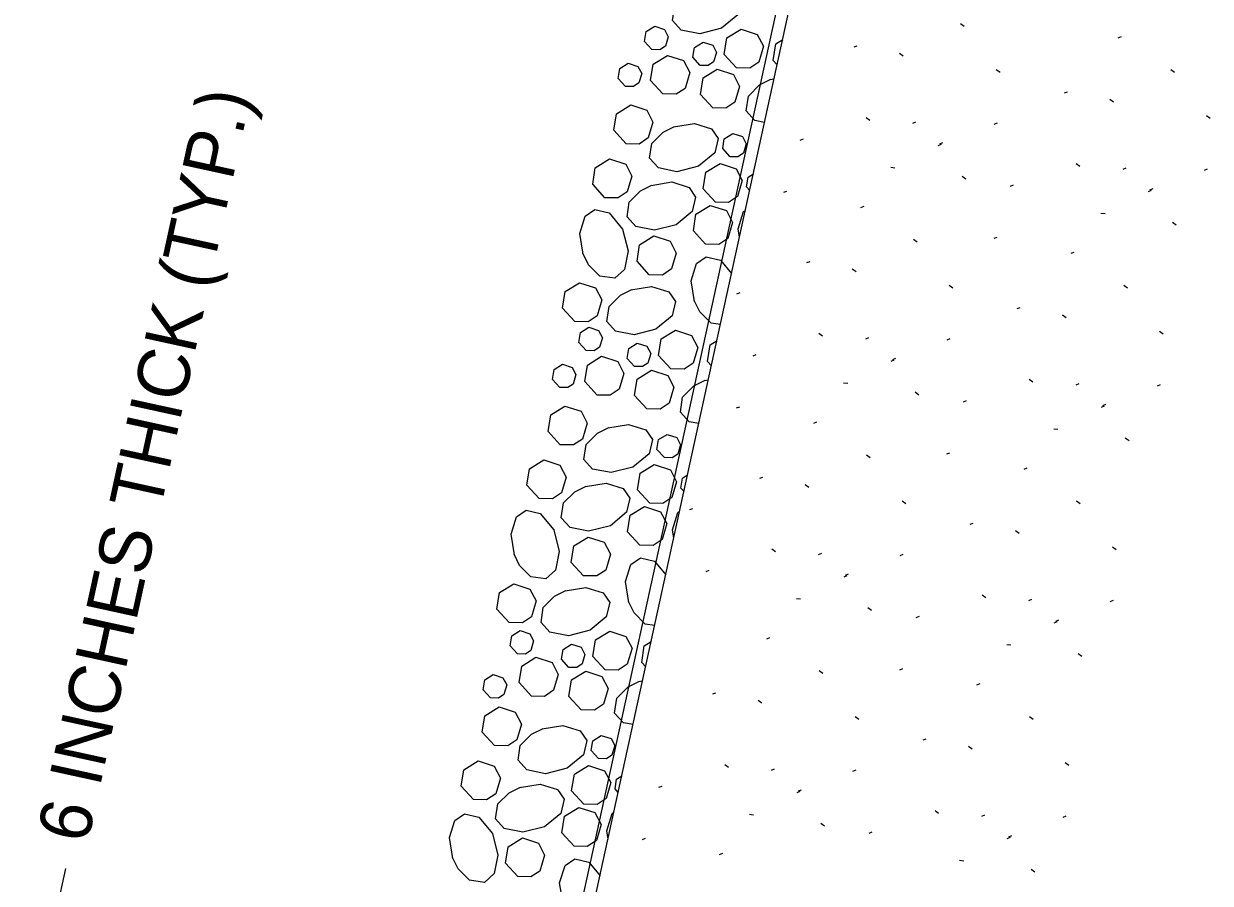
# Model space of a CAD drawing. Extents: x 2126110 to 2128246, y 1804858 to 1811658.
# Drawn here: x 2126769.3 to 2126883.6, y 1806418.7 to 1806501.5 of the extents above; entities that cross this region are included whole.
import ezdxf

# ---------------------------------------------------------------- set-up
doc = ezdxf.new("R2010")
doc.units = 0
doc.layers.add('1', color=7, linetype='Continuous')

msp = doc.modelspace()

# ---------------------------------------------------------------- linework, layer by layer
at = {"layer": '1'}
for p, q in [((2126821.03, 1806407.52), (2126844.25, 1806513.73)), ((2126822.04, 1806406.65), (2126845.41, 1806513.57)), ((2126859.94, 1806501.26), (2126859.59, 1806501.52)), ((2126874.78, 1806500.18), (2126875.08, 1806500.3)), ((2126849.32, 1806499.29), (2126849.62, 1806499.41)), ((2126854.05, 1806498.41), (2126853.69, 1806498.67)), ((2126863.39, 1806496.82), (2126863.03, 1806497.08)), ((2126880.2, 1806496.83), (2126879.85, 1806497.09)), ((2126841.22, 1806496.15), (2126841.62, 1806496.22)), ((2126869.59, 1806494.86), (2126869.89, 1806494.98)), ((2126874.31, 1806493.98), (2126873.96, 1806494.24)), ((2126850.83, 1806492.2), (2126850.48, 1806492.46)), ((2126854.98, 1806491.96), (2126855.28, 1806492.07)), ((2126862.83, 1806491.86), (2126863.13, 1806491.97)), ((2126883.65, 1806492.4), (2126883.3, 1806492.65)), ((2126844.13, 1806490.31), (2126844.43, 1806490.43)), ((2126857.44, 1806489.81), (2126857.74, 1806489.92)), ((2126857.58, 1806489.96), (2126857.87, 1806490.07)), ((2126852.85, 1806487.71), (2126853.25, 1806487.66)), ((2126871.09, 1806487.78), (2126870.74, 1806488.04)), ((2126875.25, 1806487.53), (2126875.55, 1806487.65)), ((2126883.1, 1806487.43), (2126883.39, 1806487.55)), ((2126860.1, 1806486.54), (2126859.74, 1806486.8)), ((2126842.54, 1806485.29), (2126842.84, 1806485.4)), ((2126864.4, 1806485.88), (2126864.69, 1806486)), ((2126877.7, 1806485.38), (2126878, 1806485.49)), ((2126877.84, 1806485.53), (2126878.14, 1806485.65)), ((2126849.98, 1806483.83), (2126850.28, 1806483.95)), ((2126873.11, 1806483.28), (2126873.51, 1806483.24)), ((2126880.36, 1806482.12), (2126880.01, 1806482.37)), ((2126855.4, 1806480.48), (2126855.05, 1806480.74)), ((2126862.81, 1806480.86), (2126863.11, 1806480.98)), ((2126870.24, 1806479.41), (2126870.54, 1806479.52)), ((2126844.78, 1806478.51), (2126845.08, 1806478.63)), ((2126849.51, 1806477.63), (2126849.15, 1806477.89)), ((2126858.85, 1806476.04), (2126858.49, 1806476.3)), ((2126875.66, 1806476.05), (2126875.31, 1806476.31)), ((2126838.03, 1806475.51), (2126838.33, 1806475.62)), ((2126865.05, 1806474.09), (2126865.34, 1806474.2)), ((2126869.77, 1806473.2), (2126869.42, 1806473.46)), ((2126846.29, 1806471.43), (2126845.93, 1806471.69)), ((2126879.11, 1806471.62), (2126878.76, 1806471.88)), ((2126850.44, 1806471.18), (2126850.74, 1806471.3)), ((2126858.29, 1806471.08), (2126858.59, 1806471.2)), ((2126839.59, 1806469.53), (2126839.89, 1806469.65)), ((2126852.9, 1806469.03), (2126853.2, 1806469.14)), ((2126853.04, 1806469.18), (2126853.33, 1806469.3)), ((2126834.89, 1806467.15), (2126835.28, 1806467.22)), ((2126848.31, 1806466.93), (2126848.71, 1806466.89)), ((2126866.55, 1806467), (2126866.2, 1806467.26)), ((2126870.71, 1806466.75), (2126871, 1806466.87)), ((2126855.55, 1806465.76), (2126855.2, 1806466.02)), ((2126878.55, 1806466.65), (2126878.85, 1806466.77)), ((2126838, 1806464.51), (2126838.3, 1806464.63)), ((2126859.86, 1806465.11), (2126860.15, 1806465.22)), ((2126873.16, 1806464.6), (2126873.46, 1806464.72)), ((2126873.3, 1806464.75), (2126873.6, 1806464.87)), ((2126845.44, 1806463.06), (2126845.74, 1806463.17)), ((2126868.57, 1806462.5), (2126868.97, 1806462.46)), ((2126875.82, 1806461.34), (2126875.46, 1806461.6)), ((2126850.86, 1806459.7), (2126850.51, 1806459.96)), ((2126858.27, 1806460.08), (2126858.56, 1806460.2)), ((2126840.24, 1806457.74), (2126840.54, 1806457.85)), ((2126865.7, 1806458.63), (2126866, 1806458.74)), ((2126844.97, 1806456.85), (2126844.61, 1806457.11)), ((2126854.31, 1806455.27), (2126853.95, 1806455.53)), ((2126871.12, 1806455.27), (2126870.77, 1806455.53)), ((2126833.49, 1806454.73), (2126833.79, 1806454.84)), ((2126860.51, 1806453.31), (2126860.8, 1806453.42)), ((2126865.23, 1806452.42), (2126864.88, 1806452.68)), ((2126841.75, 1806450.65), (2126841.39, 1806450.91)), ((2126874.57, 1806450.84), (2126874.22, 1806451.1)), ((2126845.9, 1806450.4), (2126846.2, 1806450.52)), ((2126853.75, 1806450.3), (2126854.05, 1806450.42)), ((2126835.05, 1806448.76), (2126835.35, 1806448.87)), ((2126848.49, 1806448.4), (2126848.79, 1806448.52)), ((2126848.36, 1806448.25), (2126848.66, 1806448.37)), ((2126862.01, 1806446.22), (2126861.66, 1806446.48)), ((2126843.77, 1806446.15), (2126844.17, 1806446.11)), ((2126851.01, 1806444.99), (2126850.66, 1806445.25)), ((2126866.17, 1806445.97), (2126866.46, 1806446.09)), ((2126874.01, 1806445.87), (2126874.31, 1806445.99)), ((2126855.32, 1806444.33), (2126855.61, 1806444.44)), ((2126868.62, 1806443.82), (2126868.92, 1806443.94)), ((2126868.76, 1806443.97), (2126869.06, 1806444.09)), ((2126840.9, 1806442.28), (2126841.2, 1806442.39)), ((2126864.03, 1806441.72), (2126864.43, 1806441.68)), ((2126871.28, 1806440.56), (2126870.92, 1806440.82)), ((2126853.73, 1806439.3), (2126854.02, 1806439.42)), ((2126828.55, 1806438.16), (2126828.94, 1806438.22)), ((2126846.32, 1806438.92), (2126845.97, 1806439.18)), ((2126835.7, 1806436.96), (2126836, 1806437.07)), ((2126861.16, 1806437.85), (2126861.46, 1806437.97)), ((2126840.43, 1806436.07), (2126840.07, 1806436.33)), ((2126849.77, 1806434.49), (2126849.41, 1806434.75)), ((2126866.58, 1806434.49), (2126866.23, 1806434.75)), ((2126855.97, 1806432.53), (2126856.26, 1806432.65)), ((2126860.69, 1806431.65), (2126860.34, 1806431.91)), ((2126870.03, 1806430.06), (2126869.68, 1806430.32)), ((2126837.21, 1806429.87), (2126836.85, 1806430.13)), ((2126841.36, 1806429.62), (2126841.66, 1806429.74)), ((2126849.21, 1806429.52), (2126849.51, 1806429.64)), ((2126830.51, 1806427.98), (2126830.81, 1806428.09)), ((2126843.82, 1806427.47), (2126844.12, 1806427.59)), ((2126843.95, 1806427.62), (2126844.25, 1806427.74)), ((2126857.47, 1806425.44), (2126857.12, 1806425.7)), ((2126839.23, 1806425.37), (2126839.63, 1806425.33)), ((2126861.63, 1806425.2), (2126861.92, 1806425.31)), ((2126869.47, 1806425.09), (2126869.77, 1806425.21)), ((2126846.47, 1806424.21), (2126846.12, 1806424.47)), ((2126850.78, 1806423.55), (2126851.07, 1806423.67)), ((2126828.92, 1806422.95), (2126829.22, 1806423.07)), ((2126864.08, 1806423.04), (2126864.38, 1806423.16)), ((2126864.22, 1806423.19), (2126864.52, 1806423.31)), ((2126836.36, 1806421.5), (2126836.66, 1806421.62)), ((2126769.29, 1806401.62), (2126773.34, 1806420.14)), ((2126859.49, 1806420.94), (2126859.89, 1806420.9)), ((2126866.74, 1806419.78), (2126866.38, 1806420.04))]:
    msp.add_line(p, q, dxfattribs=at)
for points in [[(2126834.14, 1806504.88), (2126836.14, 1806505.21), (2126837.8, 1806504.69), (2126838.44, 1806503.75), (2126838.11, 1806502.38), (2126836.55, 1806501.09), (2126834.46, 1806500.56), (2126832.67, 1806500.92), (2126831.83, 1806501.85), (2126832.04, 1806503.28), (2126833.13, 1806504.37), (2126834.22, 1806504.91)], [(2126829.84, 1806499.04), (2126829.13, 1806499.81), (2126829.28, 1806500.77), (2126830.11, 1806501.28), (2126831.04, 1806500.97), (2126831.4, 1806500.28), (2126831.13, 1806499.37), (2126830.61, 1806499.02), (2126829.84, 1806499.04)], [(2126838, 1806497.27), (2126836.81, 1806498.57), (2126837.07, 1806500.16), (2126838.44, 1806501), (2126839.99, 1806500.5), (2126840.59, 1806499.35), (2126840.14, 1806497.82), (2126839.27, 1806497.25), (2126838, 1806497.28)], [(2126841.91, 1806497.57), (2126841.52, 1806498), (2126841.77, 1806499.59), (2126842.44, 1806500)], [(2126834.5, 1806497.51), (2126833.79, 1806498.29), (2126833.94, 1806499.24), (2126834.77, 1806499.75), (2126835.7, 1806499.45), (2126836.06, 1806498.76), (2126835.78, 1806497.84), (2126835.26, 1806497.5), (2126834.5, 1806497.51)], [(2126827.29, 1806495.49), (2126826.58, 1806496.26), (2126826.73, 1806497.22), (2126827.56, 1806497.73), (2126828.49, 1806497.42), (2126828.85, 1806496.73), (2126828.58, 1806495.82), (2126828.05, 1806495.47), (2126827.29, 1806495.49)], [(2126830.89, 1806494.76), (2126829.7, 1806496.05), (2126829.96, 1806497.64), (2126831.33, 1806498.48), (2126832.89, 1806497.98), (2126833.48, 1806496.83), (2126833.03, 1806495.3), (2126832.16, 1806494.73), (2126830.89, 1806494.76)], [(2126835.7, 1806493.42), (2126834.51, 1806494.71), (2126834.76, 1806496.3), (2126836.14, 1806497.15), (2126837.69, 1806496.64), (2126838.29, 1806495.49), (2126837.83, 1806493.96), (2126836.97, 1806493.39), (2126835.7, 1806493.42)], [(2126840.69, 1806492), (2126839.76, 1806492.19), (2126838.91, 1806493.12), (2126839.13, 1806494.55), (2126840.22, 1806495.64), (2126841.31, 1806496.18)], [(2126827.35, 1806489.97), (2126826.16, 1806491.26), (2126826.42, 1806492.85), (2126827.79, 1806493.7), (2126829.34, 1806493.19), (2126829.94, 1806492.05), (2126829.49, 1806490.52), (2126828.62, 1806489.94), (2126827.35, 1806489.97)], [(2126831.92, 1806491.59), (2126833.93, 1806491.92), (2126835.59, 1806491.41), (2126836.22, 1806490.47), (2126835.9, 1806489.1), (2126834.34, 1806487.8), (2126832.24, 1806487.27), (2126830.46, 1806487.63), (2126829.61, 1806488.56), (2126829.83, 1806490), (2126830.92, 1806491.09), (2126832.01, 1806491.63)], [(2126837.37, 1806488.72), (2126836.66, 1806489.5), (2126836.81, 1806490.45), (2126837.64, 1806490.96), (2126838.57, 1806490.66), (2126838.93, 1806489.97), (2126838.66, 1806489.05), (2126838.13, 1806488.7), (2126837.37, 1806488.72)], [(2126825.31, 1806484.77), (2126824.13, 1806486.06), (2126824.38, 1806487.66), (2126825.75, 1806488.5), (2126827.31, 1806488), (2126827.9, 1806486.85), (2126827.45, 1806485.32), (2126826.58, 1806484.74), (2126825.31, 1806484.77)], [(2126835.96, 1806484.33), (2126834.77, 1806485.62), (2126835.03, 1806487.22), (2126836.4, 1806488.06), (2126837.95, 1806487.56), (2126838.55, 1806486.41), (2126838.1, 1806484.88), (2126837.23, 1806484.31), (2126835.96, 1806484.33)], [(2126829.75, 1806485.95), (2126831.76, 1806486.28), (2126833.42, 1806485.76), (2126834.05, 1806484.82), (2126833.73, 1806483.45), (2126832.17, 1806482.16), (2126830.07, 1806481.63), (2126828.29, 1806481.98), (2126827.44, 1806482.91), (2126827.66, 1806484.35), (2126828.74, 1806485.44), (2126829.84, 1806485.98)], [(2126839.27, 1806485.46), (2126838.95, 1806485.8), (2126839.1, 1806486.76), (2126839.62, 1806487.07)], [(2126835.01, 1806480.29), (2126833.83, 1806481.59), (2126834.08, 1806483.18), (2126835.45, 1806484.02), (2126837.01, 1806483.52), (2126837.6, 1806482.37), (2126837.15, 1806480.84), (2126836.29, 1806480.27), (2126835.02, 1806480.29)], [(2126823.22, 1806479.32), (2126822.89, 1806481.32), (2126823.41, 1806482.98), (2126824.35, 1806483.62), (2126825.72, 1806483.3), (2126827.01, 1806481.73), (2126827.55, 1806479.64), (2126827.19, 1806477.85), (2126826.26, 1806477.01), (2126824.82, 1806477.22), (2126823.73, 1806478.31), (2126823.19, 1806479.41)], [(2126838.29, 1806480.98), (2126838.16, 1806481.77), (2126838.67, 1806483.43), (2126838.85, 1806483.55)], [(2126829.58, 1806477.35), (2126828.4, 1806478.64), (2126828.65, 1806480.23), (2126830.03, 1806481.08), (2126831.58, 1806480.57), (2126832.17, 1806479.43), (2126831.72, 1806477.9), (2126830.86, 1806477.32), (2126829.58, 1806477.35)], [(2126833.94, 1806474.77), (2126833.61, 1806476.77), (2126834.13, 1806478.43), (2126835.07, 1806479.07), (2126836.44, 1806478.75), (2126837.52, 1806477.45)], [(2126822.42, 1806472.84), (2126821.23, 1806474.14), (2126821.49, 1806475.73), (2126822.86, 1806476.57), (2126824.41, 1806476.07), (2126825.01, 1806474.92), (2126824.56, 1806473.39), (2126823.69, 1806472.82), (2126822.42, 1806472.85)], [(2126827.8, 1806475.88), (2126829.81, 1806476.21), (2126831.47, 1806475.7), (2126832.11, 1806474.76), (2126831.78, 1806473.39), (2126830.22, 1806472.09), (2126828.12, 1806471.56), (2126826.34, 1806471.92), (2126825.49, 1806472.85), (2126825.71, 1806474.29), (2126826.8, 1806475.38), (2126827.89, 1806475.92)], [(2126836.44, 1806472.54), (2126835.54, 1806472.67), (2126834.45, 1806473.76), (2126833.91, 1806474.85)], [(2126823.51, 1806470.04), (2126822.79, 1806470.81), (2126822.95, 1806471.77), (2126823.77, 1806472.28), (2126824.7, 1806471.97), (2126825.06, 1806471.28), (2126824.79, 1806470.37), (2126824.27, 1806470.02), (2126823.51, 1806470.04)], [(2126831.66, 1806468.28), (2126830.48, 1806469.57), (2126830.73, 1806471.16), (2126832.1, 1806472.01), (2126833.66, 1806471.5), (2126834.25, 1806470.35), (2126833.8, 1806468.83), (2126832.93, 1806468.25), (2126831.66, 1806468.28)], [(2126828.17, 1806468.52), (2126827.45, 1806469.29), (2126827.61, 1806470.25), (2126828.43, 1806470.75), (2126829.36, 1806470.45), (2126829.72, 1806469.76), (2126829.45, 1806468.84), (2126828.93, 1806468.5), (2126828.17, 1806468.52)], [(2126835.58, 1806468.57), (2126835.18, 1806469), (2126835.44, 1806470.59), (2126836.11, 1806471.01)], [(2126824.55, 1806465.76), (2126823.37, 1806467.05), (2126823.62, 1806468.64), (2126824.99, 1806469.49), (2126826.55, 1806468.98), (2126827.14, 1806467.84), (2126826.69, 1806466.31), (2126825.82, 1806465.73), (2126824.55, 1806465.76)], [(2126820.96, 1806466.49), (2126820.24, 1806467.26), (2126820.4, 1806468.22), (2126821.22, 1806468.73), (2126822.15, 1806468.42), (2126822.51, 1806467.73), (2126822.24, 1806466.82), (2126821.72, 1806466.47), (2126820.96, 1806466.49)], [(2126829.36, 1806464.42), (2126828.17, 1806465.71), (2126828.43, 1806467.3), (2126829.8, 1806468.15), (2126831.36, 1806467.64), (2126831.95, 1806466.5), (2126831.5, 1806464.97), (2126830.63, 1806464.39), (2126829.36, 1806464.42)], [(2126834.36, 1806463), (2126833.42, 1806463.19), (2126832.58, 1806464.12), (2126832.79, 1806465.56), (2126833.88, 1806466.65), (2126834.97, 1806467.19)], [(2126821.01, 1806460.97), (2126819.83, 1806462.26), (2126820.08, 1806463.86), (2126821.45, 1806464.7), (2126823.01, 1806464.2), (2126823.6, 1806463.05), (2126823.15, 1806461.52), (2126822.28, 1806460.95), (2126821.01, 1806460.97)], [(2126825.59, 1806462.6), (2126827.59, 1806462.93), (2126829.25, 1806462.41), (2126829.89, 1806461.47), (2126829.56, 1806460.1), (2126828, 1806458.81), (2126825.91, 1806458.28), (2126824.12, 1806458.63), (2126823.28, 1806459.56), (2126823.49, 1806461), (2126824.58, 1806462.09), (2126825.67, 1806462.63)], [(2126831.04, 1806459.73), (2126830.32, 1806460.5), (2126830.48, 1806461.46), (2126831.3, 1806461.96), (2126832.23, 1806461.66), (2126832.59, 1806460.97), (2126832.32, 1806460.05), (2126831.8, 1806459.71), (2126831.04, 1806459.73)], [(2126818.98, 1806455.78), (2126817.79, 1806457.07), (2126818.04, 1806458.66), (2126819.42, 1806459.5), (2126820.97, 1806459), (2126821.57, 1806457.85), (2126821.12, 1806456.32), (2126820.25, 1806455.75), (2126818.98, 1806455.78)], [(2126829.62, 1806455.34), (2126828.44, 1806456.63), (2126828.69, 1806458.22), (2126830.06, 1806459.07), (2126831.62, 1806458.56), (2126832.21, 1806457.41), (2126831.76, 1806455.89), (2126830.89, 1806455.31), (2126829.62, 1806455.34)], [(2126832.93, 1806456.46), (2126832.61, 1806456.8), (2126832.77, 1806457.76), (2126833.28, 1806458.08)], [(2126823.42, 1806456.95), (2126825.42, 1806457.28), (2126827.08, 1806456.76), (2126827.72, 1806455.82), (2126827.39, 1806454.46), (2126825.83, 1806453.16), (2126823.74, 1806452.63), (2126821.95, 1806452.99), (2126821.1, 1806453.92), (2126821.32, 1806455.36), (2126822.41, 1806456.44), (2126823.5, 1806456.98)], [(2126816.58, 1806450.35), (2126816.26, 1806452.35), (2126816.77, 1806454.01), (2126817.71, 1806454.65), (2126819.08, 1806454.33), (2126820.37, 1806452.76), (2126820.91, 1806450.67), (2126820.55, 1806448.88), (2126819.62, 1806448.04), (2126818.18, 1806448.25), (2126817.09, 1806449.34), (2126816.55, 1806450.43)], [(2126828.68, 1806451.3), (2126827.49, 1806452.59), (2126827.75, 1806454.18), (2126829.12, 1806455.03), (2126830.67, 1806454.52), (2126831.27, 1806453.37), (2126830.82, 1806451.85), (2126829.95, 1806451.27), (2126828.68, 1806451.3)], [(2126831.95, 1806451.98), (2126831.82, 1806452.78), (2126832.34, 1806454.44), (2126832.51, 1806454.56)], [(2126823.25, 1806448.35), (2126822.06, 1806449.64), (2126822.32, 1806451.24), (2126823.69, 1806452.08), (2126825.24, 1806451.58), (2126825.84, 1806450.43), (2126825.39, 1806448.9), (2126824.52, 1806448.33), (2126823.25, 1806448.35)], [(2126827.61, 1806445.77), (2126827.28, 1806447.78), (2126827.79, 1806449.44), (2126828.74, 1806450.08), (2126830.1, 1806449.75), (2126831.18, 1806448.45)], [(2126816.08, 1806443.85), (2126814.9, 1806445.14), (2126815.15, 1806446.73), (2126816.52, 1806447.58), (2126818.08, 1806447.07), (2126818.67, 1806445.92), (2126818.22, 1806444.4), (2126817.35, 1806443.82), (2126816.08, 1806443.85)], [(2126821.47, 1806446.89), (2126823.47, 1806447.22), (2126825.13, 1806446.7), (2126825.77, 1806445.76), (2126825.44, 1806444.39), (2126823.88, 1806443.1), (2126821.79, 1806442.57), (2126820, 1806442.92), (2126819.16, 1806443.85), (2126819.37, 1806445.29), (2126820.46, 1806446.38), (2126821.55, 1806446.92)], [(2126830.11, 1806443.54), (2126829.2, 1806443.68), (2126828.11, 1806444.77), (2126827.58, 1806445.86)], [(2126816.89, 1806440.82), (2126816.18, 1806441.6), (2126816.33, 1806442.55), (2126817.15, 1806443.06), (2126818.08, 1806442.76), (2126818.44, 1806442.07), (2126818.17, 1806441.15), (2126817.65, 1806440.8), (2126816.89, 1806440.82)], [(2126825.33, 1806439.28), (2126824.14, 1806440.57), (2126824.39, 1806442.17), (2126825.77, 1806443.01), (2126827.32, 1806442.51), (2126827.92, 1806441.36), (2126827.46, 1806439.83), (2126826.6, 1806439.25), (2126825.33, 1806439.28)], [(2126821.83, 1806439.52), (2126821.12, 1806440.3), (2126821.27, 1806441.25), (2126822.09, 1806441.76), (2126823.03, 1806441.46), (2126823.38, 1806440.77), (2126823.11, 1806439.85), (2126822.59, 1806439.5), (2126821.83, 1806439.52)], [(2126829.24, 1806439.58), (2126828.85, 1806440), (2126829.1, 1806441.6), (2126829.77, 1806442.01)], [(2126818.22, 1806436.76), (2126817.03, 1806438.05), (2126817.29, 1806439.65), (2126818.66, 1806440.49), (2126820.21, 1806439.99), (2126820.81, 1806438.84), (2126820.36, 1806437.31), (2126819.49, 1806436.73), (2126818.22, 1806436.76)], [(2126814.28, 1806436.58), (2126813.57, 1806437.36), (2126813.72, 1806438.31), (2126814.55, 1806438.82), (2126815.48, 1806438.52), (2126815.84, 1806437.83), (2126815.56, 1806436.91), (2126815.04, 1806436.57), (2126814.28, 1806436.58)], [(2126823.02, 1806435.42), (2126821.84, 1806436.71), (2126822.09, 1806438.31), (2126823.46, 1806439.15), (2126825.02, 1806438.65), (2126825.61, 1806437.5), (2126825.16, 1806435.97), (2126824.29, 1806435.39), (2126823.02, 1806435.42)], [(2126828.02, 1806434.01), (2126827.09, 1806434.19), (2126826.24, 1806435.12), (2126826.45, 1806436.56), (2126827.54, 1806437.65), (2126828.64, 1806438.19)], [(2126814.68, 1806431.98), (2126813.49, 1806433.27), (2126813.74, 1806434.86), (2126815.12, 1806435.71), (2126816.67, 1806435.2), (2126817.27, 1806434.05), (2126816.81, 1806432.53), (2126815.95, 1806431.95), (2126814.68, 1806431.98)], [(2126819.25, 1806433.6), (2126821.25, 1806433.93), (2126822.91, 1806433.41), (2126823.55, 1806432.47), (2126823.23, 1806431.11), (2126821.66, 1806429.81), (2126819.57, 1806429.28), (2126817.79, 1806429.64), (2126816.94, 1806430.57), (2126817.15, 1806432), (2126818.24, 1806433.09), (2126819.34, 1806433.63)], [(2126824.7, 1806430.73), (2126823.99, 1806431.5), (2126824.14, 1806432.46), (2126824.96, 1806432.97), (2126825.9, 1806432.66), (2126826.25, 1806431.98), (2126825.98, 1806431.06), (2126825.46, 1806430.71), (2126824.7, 1806430.73)], [(2126812.64, 1806426.78), (2126811.45, 1806428.07), (2126811.71, 1806429.66), (2126813.08, 1806430.51), (2126814.63, 1806430), (2126815.23, 1806428.85), (2126814.78, 1806427.33), (2126813.91, 1806426.75), (2126812.64, 1806426.78)], [(2126823.29, 1806426.34), (2126822.1, 1806427.63), (2126822.36, 1806429.22), (2126823.73, 1806430.07), (2126825.28, 1806429.57), (2126825.88, 1806428.42), (2126825.43, 1806426.89), (2126824.56, 1806426.31), (2126823.29, 1806426.34)], [(2126826.59, 1806427.47), (2126826.28, 1806427.81), (2126826.43, 1806428.76), (2126826.95, 1806429.08)], [(2126817.08, 1806427.96), (2126819.08, 1806428.28), (2126820.74, 1806427.77), (2126821.38, 1806426.83), (2126821.06, 1806425.46), (2126819.49, 1806424.17), (2126817.4, 1806423.63), (2126815.61, 1806423.99), (2126814.77, 1806424.92), (2126814.98, 1806426.36), (2126816.07, 1806427.45), (2126817.17, 1806427.99)], [(2126822.34, 1806422.3), (2126821.16, 1806423.59), (2126821.41, 1806425.19), (2126822.78, 1806426.03), (2126824.34, 1806425.53), (2126824.93, 1806424.38), (2126824.48, 1806422.85), (2126823.61, 1806422.27), (2126822.34, 1806422.3)], [(2126810.66, 1806421.12), (2126810.34, 1806423.12), (2126810.85, 1806424.78), (2126811.79, 1806425.42), (2126813.16, 1806425.09), (2126814.46, 1806423.53), (2126814.99, 1806421.44), (2126814.63, 1806419.65), (2126813.7, 1806418.81), (2126812.26, 1806419.02), (2126811.17, 1806420.11), (2126810.63, 1806421.2)], [(2126825.61, 1806422.98), (2126825.48, 1806423.78), (2126826, 1806425.44), (2126826.18, 1806425.56)], [(2126816.91, 1806419.36), (2126815.73, 1806420.65), (2126815.98, 1806422.24), (2126817.35, 1806423.09), (2126818.91, 1806422.58), (2126819.5, 1806421.43), (2126819.05, 1806419.9), (2126818.18, 1806419.33), (2126816.91, 1806419.36)], [(2126821.27, 1806416.78), (2126820.94, 1806418.78), (2126821.46, 1806420.44), (2126822.4, 1806421.08), (2126823.77, 1806420.75), (2126824.84, 1806419.45)]]:
    msp.add_lwpolyline(points, dxfattribs=at)

# ---------------------------------------------------------------- texts
msp.add_text('6 INCHES THICK (TYP.)', height=5, rotation=77.6736, dxfattribs=at).set_placement((2126775.43, 1806422.43))

doc.saveas('drawing.dxf')
